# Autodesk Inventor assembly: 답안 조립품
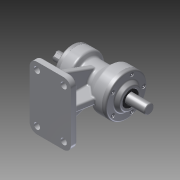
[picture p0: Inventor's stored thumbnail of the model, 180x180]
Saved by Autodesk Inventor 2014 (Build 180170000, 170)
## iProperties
Created: 2015-08
Part Number: 답안 조립품
Document SubType Name: Assembly
Designer: SEC
Author: SEC
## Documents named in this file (10)
- C:\Users\SEC\Desktop\450805V1002\답안 조립품.iam
- C:\Users\SEC\Desktop\450805V1002\축.ipt
- C:\Users\SEC\Desktop\450805V1002\베어링 6203.ipt
- C:\Users\SEC\Desktop\450805V1002\베어링 6205.ipt
- C:\Users\SEC\Desktop\450805V1002\본체.ipt
- C:\Users\SEC\Desktop\450805V1002\뒤커버.ipt
- C:\Users\SEC\Desktop\450805V1002\앞커버.ipt
- C:\Users\SEC\Desktop\450805V1002\M4x0.5.ipt
- C:\Users\SEC\Desktop\450805V1002\오일실 .ipt
- 오일실 .ipt
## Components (10 placed, 1 different names)
1. M4x0.5:1
2. M4x0.5:2
3. M4x0.5:3
4. M4x0.5:4
5. M4x0.5:5
6. M4x0.5:6
7. M4x0.5:7
8. M4x0.5:8
9. M4x0.5:9
10. M4x0.5:10
